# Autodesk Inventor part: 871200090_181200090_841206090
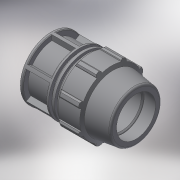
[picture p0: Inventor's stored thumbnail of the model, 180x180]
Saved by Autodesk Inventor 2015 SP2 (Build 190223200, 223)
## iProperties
Created: 2017-02
Part Number: 871200090_181200090_841206090
Material: Generic
Description: PLASSON END PLUG 90
Document SubType Name: Modeling
Designer: KIM
Mass: 947.017 g
Surface Area: 1382.98 cm^2
Volume: 947.017 cm^3
Density: 1 g/cm^3
Appearance: Default
Author: Кирилл
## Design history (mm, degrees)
derived "87120.ipt"
feature "Solid1::87120.ipt"
tag "TaggingFeature1"
body "Solid1"
other parameters: "d4" = 30.14286, "d5" = 52.75, "d7" = 152, "d8" = 114, "d9" = 30.14286, "d11" = 6.02857, "d12" = 121.6, "d13" = 120 deg, "d14" = 117, "d15" = 8 deg, "d16" = 136.8, "d18" = 4.5, "d19" = 35 deg, "d20" = 17.5 deg, "d21" = 141.36, "d23" = 0, "d25" = 360 deg, "d27" = 3.04, "d34" = 7.6, "d36" = 0, "d42" = 52.75, "d43" = 4.56, "d46" = 2.7, "d53" = 1.8, "d55" = 360 deg, "d59" = 52.75, "d64" = 211, "d66" = 19.76, "d67" = 12.16, "d68" = 169, "d70" = 24.11429, "d71" = 6.02857, "d72" = 134.064, "d75" = 12.05714, "E_" = 152, "H_" = 211, "l_" = 169
